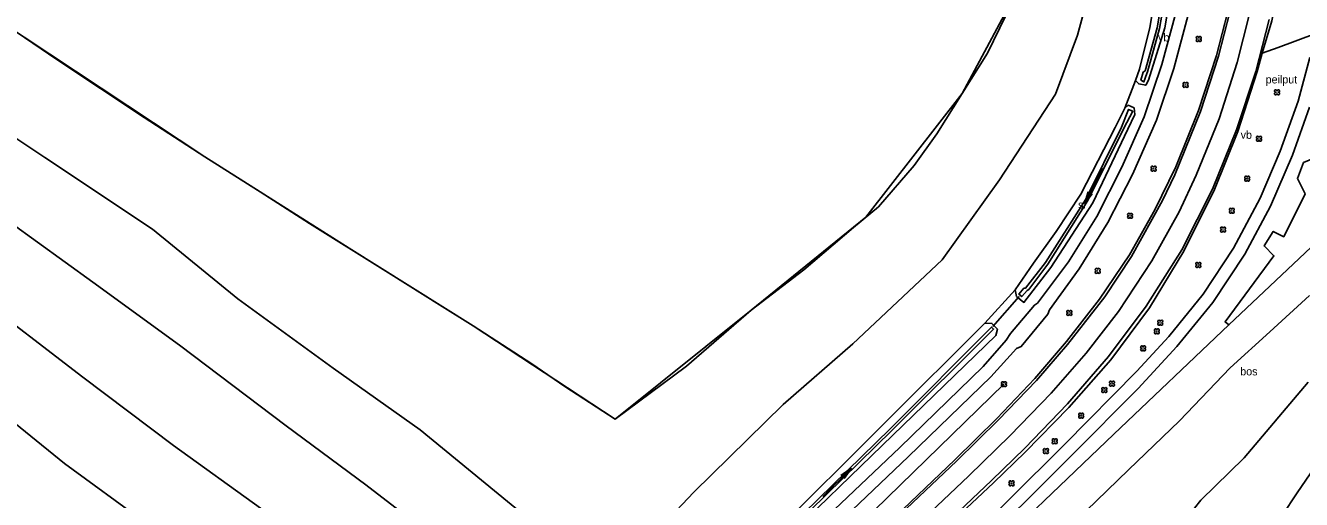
# Model space of a CAD drawing. Extents: x 154825 to 158680, y 370717 to 378075.
# Drawn here: x 157815 to 157974.4, y 372426.3 to 372485.5 of the extents above; entities that cross this region are included whole.
import ezdxf

# ---------------------------------------------------------------- set-up
doc = ezdxf.new("R2010")
doc.units = 0
for name, color, linetype in [('boom', 7, 'Continuous'), ('bos(vs)', 7, 'Continuous'), ('cultuurscheiding', 7, 'Continuous'), ('deelstreep(9-3)', 7, 'Continuous'), ('duiker lijn', 7, 'Continuous'), ('hoogteverschillijn', 7, 'Continuous'), ('insteek sloot', 7, 'Continuous'), ('kantstreep', 7, 'Continuous'), ('maaiveldlijn algemeen - gesloten verharding', 7, 'Continuous'), ('maaiveldlijn algemeen - open verharding', 7, 'Continuous'), ('peilput', 7, 'Continuous'), ('raster - hek', 7, 'Continuous'), ('Sloot bodem', 7, 'Continuous'), ('sloot(vs)', 7, 'Continuous'), ('stroomrichting  watergangen', 7, 'Continuous'), ('verkeersb_z kabel', 7, 'Continuous'), ('vlak_akkerland', 7, 'Continuous'), ('vlak_Bos', 7, 'Continuous'), ('vlak_Grazige_vegetatie', 7, 'Continuous')]:
    doc.layers.add(name, color=color, linetype=linetype)

msp = doc.modelspace()

# ---------------------------------------------------------------- linework, layer by layer
at = {"layer": 'boom'}
msp.add_lwpolyline([(157937.25, 372440.7), (157921.08, 372424.96), (157899.21, 372404.5)], dxfattribs=at)
for centre in [(157961.6, 372483.8), (157959.94, 372478.08), (157971.38, 372477.16), (157969.13, 372471.34), (157955.95, 372467.62), (157967.64, 372466.36), (157953.02, 372461.73), (157965.73, 372462.35), (157964.64, 372460.01), (157961.54, 372455.58), (157948.98, 372454.85), (157945.43, 372449.59), (157956.36, 372447.29), (157956.78, 372448.36), (157954.65, 372445.16), (157937.25, 372440.7), (157950.76, 372440.76), (157949.8, 372439.96), (157946.9, 372436.76), (157943.6, 372433.57), (157942.49, 372432.33), (157938.2, 372428.31)]:
    msp.add_circle(centre, 0.006, dxfattribs=at)
for centre, start, end in [((157961.44, 372483.96), 357.075, 272.925), ((157961.44, 372483.65), 87.075, 2.925), ((157961.75, 372483.96), 267.075, 182.925), ((157961.75, 372483.65), 177.075, 92.925), ((157959.78, 372478.24), 357.075, 272.925), ((157959.78, 372477.92), 87.075, 2.925), ((157960.1, 372478.24), 267.075, 182.925), ((157960.1, 372477.92), 177.075, 92.925), ((157971.22, 372477.31), 357.075, 272.925), ((157971.54, 372477.31), 267.075, 182.925), ((157971.22, 372477), 87.075, 2.925), ((157971.54, 372477), 177.075, 92.925), ((157968.97, 372471.5), 357.075, 272.925), ((157968.97, 372471.19), 87.075, 2.925), ((157969.29, 372471.5), 267.075, 182.925), ((157969.29, 372471.19), 177.075, 92.925), ((157955.79, 372467.77), 357.075, 272.925), ((157956.11, 372467.77), 267.075, 182.925), ((157955.79, 372467.46), 87.075, 2.925), ((157956.11, 372467.46), 177.075, 92.925), ((157967.49, 372466.52), 357.075, 272.925), ((157967.49, 372466.2), 87.075, 2.925), ((157967.8, 372466.52), 267.075, 182.925), ((157967.8, 372466.2), 177.075, 92.925), ((157952.86, 372461.88), 357.075, 272.925), ((157952.86, 372461.57), 87.075, 2.925), ((157953.17, 372461.88), 267.075, 182.925), ((157953.17, 372461.57), 177.075, 92.925), ((157965.57, 372462.51), 357.075, 272.925), ((157965.57, 372462.19), 87.075, 2.925), ((157965.88, 372462.51), 267.075, 182.925), ((157965.88, 372462.19), 177.075, 92.925), ((157964.48, 372460.17), 357.075, 272.925), ((157964.48, 372459.85), 87.075, 2.925), ((157964.8, 372460.17), 267.075, 182.925), ((157964.8, 372459.85), 177.075, 92.925), ((157948.82, 372455.01), 357.075, 272.925), ((157949.14, 372455.01), 267.075, 182.925), ((157961.38, 372455.74), 357.075, 272.925), ((157961.38, 372455.43), 87.075, 2.925), ((157961.7, 372455.74), 267.075, 182.925), ((157961.7, 372455.43), 177.075, 92.925), ((157948.82, 372454.69), 87.075, 2.925), ((157949.14, 372454.69), 177.075, 92.925), ((157945.27, 372449.75), 357.075, 272.925), ((157945.27, 372449.44), 87.075, 2.925), ((157945.59, 372449.75), 267.075, 182.925), ((157945.59, 372449.44), 177.075, 92.925), ((157956.62, 372448.52), 357.075, 272.925), ((157956.94, 372448.52), 267.075, 182.925), ((157956.2, 372447.45), 357.075, 272.925), ((157956.2, 372447.13), 87.075, 2.925), ((157956.51, 372447.45), 267.075, 182.925), ((157956.51, 372447.13), 177.075, 92.925), ((157956.62, 372448.2), 87.075, 2.925), ((157956.94, 372448.2), 177.075, 92.925), ((157954.49, 372445.32), 357.075, 272.925), ((157954.8, 372445.32), 267.075, 182.925), ((157954.49, 372445), 87.075, 2.925), ((157954.8, 372445), 177.075, 92.925), ((157937.09, 372440.85), 357.075, 272.925), ((157937.09, 372440.54), 87.075, 2.925), ((157937.41, 372440.85), 267.075, 182.925), ((157937.41, 372440.54), 177.075, 92.925), ((157950.6, 372440.91), 357.075, 272.925), ((157950.6, 372440.6), 87.075, 2.925), ((157950.92, 372440.91), 267.075, 182.925), ((157950.92, 372440.6), 177.075, 92.925), ((157949.64, 372440.11), 357.075, 272.925), ((157949.64, 372439.8), 87.075, 2.925), ((157949.96, 372440.11), 267.075, 182.925), ((157949.96, 372439.8), 177.075, 92.925), ((157946.75, 372436.92), 357.075, 272.925), ((157946.75, 372436.6), 87.075, 2.925), ((157947.06, 372436.92), 267.075, 182.925), ((157947.06, 372436.6), 177.075, 92.925), ((157943.45, 372433.72), 357.075, 272.925), ((157943.45, 372433.41), 87.075, 2.925), ((157943.76, 372433.72), 267.075, 182.925), ((157943.76, 372433.41), 177.075, 92.925), ((157942.33, 372432.49), 357.075, 272.925), ((157942.33, 372432.17), 87.075, 2.925), ((157942.65, 372432.49), 267.075, 182.925), ((157942.65, 372432.17), 177.075, 92.925), ((157938.04, 372428.47), 357.075, 272.925), ((157938.04, 372428.15), 87.075, 2.925), ((157938.36, 372428.47), 267.075, 182.925), ((157938.36, 372428.15), 177.075, 92.925)]:
    msp.add_arc(centre, 0.158, start, end, dxfattribs=at)
at = {"layer": 'bos(vs)'}
msp.add_lwpolyline([(157991.01, 372472.3), (157988.03, 372476.61), (157981.58, 372483.22), (157979.12, 372480.89), (157980.07, 372479.08), (157976.61, 372469.17), (157974.7, 372468.37), (157973.91, 372466.38), (157974.87, 372464.48), (157972.22, 372459.1), (157970.9, 372459.77), (157969.76, 372457.97), (157970.99, 372456.73), (157964.89, 372448.46), (157965.36, 372448.1)], dxfattribs=at)
at = {"layer": 'cultuurscheiding'}
for points in [[(157952.35, 372475.19), (157953.67, 372478.63)], [(157934.88, 372448.33), (157938.65, 372452.47)]]:
    msp.add_lwpolyline(points, dxfattribs=at)
at = {"layer": 'deelstreep(9-3)'}
msp.add_lwpolyline([(157967.9, 372486.8), (157966.4, 372480.87), (157964.14, 372473.83), (157961.28, 372466.81), (157959.13, 372462.23), (157955.73, 372456.1), (157951.58, 372449.77), (157947.51, 372444.57), (157943.17, 372439.56), (157938.03, 372434.28), (157932.88, 372429.26), (157917.8, 372414.96), (157900.57, 372398.73)], dxfattribs=at)
at = {"layer": 'duiker lijn'}
msp.add_lwpolyline([(157935.88, 372447.9), (157939.16, 372451.65)], dxfattribs=at)
at = {"layer": 'hoogteverschillijn'}
for points in [[(157949.06, 372493.97), (157946.43, 372484.27), (157943.68, 372476.9), (157936.71, 372466.22), (157929.52, 372456.21), (157918.38, 372445.73), (157909.69, 372438.14), (157898.49, 372427.19), (157888.26, 372416.39), (157876.85, 372424.72), (157864.32, 372434.98), (157853.47, 372442.68), (157841.56, 372451.35), (157830.89, 372460.06), (157817.44, 372469), (157806.91, 372476.01)], [(157810.8, 372486.76), (157818.91, 372481.27), (157829.84, 372473.99), (157837.4, 372469.1), (157844.34, 372464.74), (157850.48, 372460.77), (157860.38, 372454.6), (157867.08, 372450.39), (157870.96, 372447.97), (157878.26, 372443.24), (157882.38, 372440.39), (157888.67, 372436.33), (157897.61, 372442.95), (157905.68, 372449.95), (157912.26, 372454.96), (157918.46, 372460.25), (157921.59, 372462.85), (157926.05, 372468.02), (157928.88, 372471.98), (157935.2, 372482.04), (157939.78, 372491.5)], [(157881.47, 372407.9), (157872.69, 372415.27), (157866.4, 372421.3), (157857.53, 372428.1), (157847.58, 372435.5), (157834.25, 372445.57), (157823.42, 372453.44), (157813.05, 372460.94)], [(157808.27, 372452.22), (157822.19, 372441.57), (157833.49, 372433.04), (157844.36, 372425.2), (157854.75, 372417.01), (157862.66, 372410.39), (157874.45, 372400.64), (157866.59, 372392.5), (157855.13, 372401.58), (157847.65, 372408.81), (157837.38, 372416.14), (157829.91, 372423.46), (157819.89, 372430.77), (157810.1, 372438.7)], [(157975.42, 372451.75), (157970.46, 372447.24), (157965.5, 372442.73), (157959.18, 372436.11), (157952.82, 372429.98), (157944.87, 372422.31), (157934.73, 372412.55), (157929.45, 372407.46), (157937.32, 372400.74), (157942.35, 372406.7), (157949.83, 372413.18), (157956.32, 372419.2), (157961.87, 372426.2), (157967.28, 372431.48), (157975.28, 372440.95)], [(157983.15, 372370.82), (157972.8, 372377.86), (157967.18, 372381.36), (157958.84, 372386.99), (157945.2, 372395.77), (157958.44, 372407.85), (157965.25, 372414.93), (157970.16, 372421.45), (157973.9, 372427.12), (157978.77, 372434.26)]]:
    msp.add_lwpolyline(points, dxfattribs=at)
at = {"layer": 'insteek sloot'}
for points in [[(157954.19, 372539.22), (157953.23, 372540.06), (157952.94, 372539.09), (157953.29, 372537.7), (157955.47, 372527.74), (157956.42, 372522.74), (157957.47, 372512.36), (157957.5, 372502.78), (157956.95, 372493.75), (157955.48, 372485.23), (157954.2, 372480.04), (157953.67, 372478.63)], [(157953.67, 372478.63), (157954.1, 372478.2), (157954.97, 372478.04), (157955.3, 372478.66), (157957.37, 372485.22), (157958.74, 372493.47), (157959.47, 372502.93), (157959.54, 372512.25), (157958.49, 372522.7), (157957.48, 372527.63), (157955.84, 372533.76), (157954.62, 372537.88), (157954.19, 372539.22)], [(157938.65, 372452.47), (157938.83, 372451.66), (157939.75, 372450.9), (157943.12, 372455.26), (157948.34, 372463.35), (157952.74, 372472.54), (157953.6, 372474.39), (157953.51, 372475.2), (157952.78, 372475.53), (157952.35, 372475.19)], [(157952.35, 372475.19), (157951.17, 372472.75), (157946.88, 372464.44), (157943.76, 372459.76), (157940.93, 372455.81), (157938.65, 372452.47)], [(157893.76, 372408), (157893.83, 372407.41), (157894.35, 372406.92), (157894.88, 372407.08), (157908.69, 372420.09), (157923.39, 372434.34), (157936.24, 372446.79), (157936.43, 372447.55), (157935.76, 372448.29), (157934.88, 372448.33)], [(157893.76, 372408), (157908.11, 372421.68), (157922.48, 372435.99), (157934.88, 372448.33)]]:
    msp.add_lwpolyline(points, dxfattribs=at)
at = {"layer": 'kantstreep'}
for points in [[(157811.11, 372314.18), (157819.16, 372322.72), (157827.26, 372331.17), (157835.64, 372339.76), (157843.77, 372347.86), (157852.31, 372356.24), (157869.21, 372372.45), (157886.33, 372388.55), (157895.28, 372396.97), (157898.87, 372400.4), (157916.5, 372417.04), (157931.32, 372431.09), (157936.57, 372436.22), (157941.31, 372441.16), (157945.2, 372445.65), (157949.85, 372451.61), (157953.2, 372456.66), (157957.05, 372463.64), (157958.6, 372466.86), (157961.83, 372474.76), (157964.06, 372481.67), (157965.46, 372487.18)], [(157970.4, 372486.24), (157968.71, 372479.75), (157966.29, 372472.47), (157963.29, 372465.06), (157959.47, 372457.49), (157955.04, 372450.45), (157950.31, 372444.14), (157945.19, 372438.22), (157939.88, 372432.7), (157935.68, 372428.65), (157919.64, 372413.43), (157902.02, 372396.85), (157893.16, 372388.45), (157875.35, 372371.69), (157863.62, 372360.57), (157853.07, 372350.36), (157843.79, 372341.19), (157832.37, 372329.62), (157817.57, 372314.15), (157804.62, 372300.14)]]:
    msp.add_lwpolyline(points, dxfattribs=at)
at = {"layer": 'maaiveldlijn algemeen - gesloten verharding'}
for points in [[(157972.32, 372497.17), (157971.97, 372493.12), (157971.27, 372488.8), (157970.71, 372486.1), (157969.53, 372482.06)], [(157864.5, 372368.13), (157869.15, 372372.56), (157886.25, 372388.63), (157895.13, 372397.07), (157898.79, 372400.56), (157916.39, 372417.15), (157931.13, 372431.24), (157936.35, 372436.39), (157941.12, 372441.4), (157945.09, 372446.03), (157949.21, 372451.3), (157952.94, 372456.85), (157956.1, 372462.48), (157958.74, 372467.86), (157961.57, 372474.9), (157963.8, 372481.74), (157965.22, 372487.24), (157965.93, 372491.28), (157966.21, 372493.54), (157966.4, 372495.02)], [(157961.74, 372494.05), (157961.59, 372493.12), (157960.26, 372486.82), (157958.48, 372480.12), (157956.3, 372473.66), (157953.33, 372466.9), (157950.22, 372460.87), (157946.65, 372455.09), (157942.95, 372449.98), (157942.75, 372449.44), (157939.41, 372445.41), (157938.84, 372445.13), (157935.6, 372441.6), (157925.35, 372431.65), (157910.36, 372417.43), (157897.25, 372404.98), (157896.96, 372404.48), (157893.44, 372401.18), (157892.88, 372400.89), (157876.85, 372385.69), (157860.57, 372370.22), (157860.56, 372369.75)], [(157876.55, 372387.59), (157892.12, 372402.31), (157892.47, 372402.88), (157895.58, 372405.9), (157896.14, 372406.21), (157909.53, 372418.83), (157924.24, 372432.78), (157934.64, 372442.91), (157937.52, 372446.2), (157938.07, 372447.02), (157941.07, 372450.57), (157941.43, 372450.8), (157945.33, 372455.97), (157948.85, 372461.64), (157951.98, 372467.8), (157954.79, 372474.1), (157956.96, 372480.62), (157958.72, 372487.07)], [(157969.53, 372482.06), (157968.91, 372479.75), (157966.46, 372472.24), (157963.55, 372465), (157959.74, 372457.31), (157955.42, 372450.24), (157950.59, 372443.72), (157945.35, 372437.77), (157939.89, 372432.18), (157935.93, 372428.36), (157919.65, 372413.08), (157902.19, 372396.75), (157893.25, 372388.19), (157875.56, 372371.65), (157863.74, 372360.45), (157853.15, 372350.29), (157843.8, 372340.99), (157832.49, 372329.54), (157817.76, 372314.12), (157804.8, 372300.01), (157792.67, 372286.53), (157785.23, 372277.85), (157775.12, 372265.78), (157770.05, 372259.54)], [(157821.24, 372312.61), (157834, 372325.93), (157845.57, 372337.78), (157856.3, 372348.32), (157871.24, 372362.53), (157885.82, 372376.21), (157886.18, 372376.92), (157889.48, 372379.96), (157889.94, 372380.16), (157901.38, 372390.87), (157901.57, 372391.35), (157905.18, 372394.73), (157905.62, 372394.85), (157918.55, 372407.05), (157931.01, 372419.43), (157944.83, 372433.17), (157953.86, 372442.31), (157957.84, 372446.64), (157962.14, 372451.92), (157965.94, 372457.7), (157969.25, 372463.91), (157971.77, 372469.79), (157974.02, 372476.05), (157975.48, 372481.48)], [(157821.31, 372310.37), (157835.13, 372324.82), (157846.78, 372336.7), (157857.51, 372347.3), (157872.11, 372361.18), (157887.49, 372375.54), (157888.21, 372375.92), (157890.86, 372378.33), (157891.26, 372379.11), (157902.34, 372389.53), (157903.65, 372390.63), (157906.48, 372393.2), (157906.76, 372393.65), (157919.78, 372406.01), (157932.74, 372418.86), (157945.75, 372431.83), (157954.03, 372440.15), (157958.86, 372445.41), (157963.37, 372450.88), (157967.35, 372456.93), (157970.57, 372462.94), (157973.29, 372469.28), (157975.44, 372475.29)]]:
    msp.add_lwpolyline(points, dxfattribs=at)
at = {"layer": 'maaiveldlijn algemeen - open verharding'}
msp.add_lwpolyline([(157969.53, 372482.06), (157971.52, 372482.76), (157976.08, 372484.46)], dxfattribs=at)
at = {"layer": 'raster - hek'}
for points in [[(157991.01, 372472.3), (157965.36, 372448.1)], [(157965.36, 372448.1), (157951, 372434.44), (157932.61, 372416.87), (157926.64, 372411.07)]]:
    msp.add_lwpolyline(points, dxfattribs=at)
at = {"layer": 'Sloot bodem'}
for points in [[(157954.75, 372478.44), (157954.37, 372478.65), (157954.65, 372479.67), (157954.88, 372479.84), (157956.41, 372485.22), (157957.76, 372493.33), (157958.58, 372502.83), (157958.53, 372512.12), (157957.37, 372522.98), (157956.44, 372527.35), (157955.19, 372532.77), (157953.65, 372538.14), (157953.96, 372538.26), (157955.48, 372532.84), (157956.79, 372527.41), (157957.7, 372523.02), (157958.86, 372512.11), (157958.88, 372502.81), (157958.09, 372493.3), (157956.68, 372485.12), (157955.17, 372479.73), (157955.1, 372479.5), (157954.75, 372478.44)], [(157952.82, 372475.01), (157953.35, 372474.78), (157952.24, 372472.68), (157947.72, 372463.62), (157942.72, 372455.67), (157940.35, 372452.53), (157940.16, 372452.38), (157939.47, 372451.64), (157939.13, 372451.92), (157939.74, 372452.68), (157939.96, 372452.69), (157942.45, 372455.88), (157947.48, 372463.79), (157951.94, 372472.8), (157952.82, 372475.01)], [(157894.07, 372407.77), (157894.42, 372407.41), (157895.34, 372408.18), (157908.87, 372420.82), (157923.27, 372434.95), (157935.97, 372447.57), (157935.71, 372447.82), (157923.09, 372435.16), (157908.64, 372421.05), (157895.19, 372408.43), (157894.07, 372407.77)]]:
    msp.add_lwpolyline(points, dxfattribs=at)
at = {"layer": 'stroomrichting  watergangen'}
for p, q in [((157949.58, 372467.66), (157947.31, 372463.21)), ((157947.31, 372463.21), (157947.77, 372464.72)), ((157947.33, 372463.22), (157948.28, 372464.48)), ((157914.64, 372426.68), (157918.19, 372430.19)), ((157918.17, 372430.19), (157916.87, 372429.29)), ((157918.19, 372430.19), (157917.28, 372428.9))]:
    msp.add_line(p, q, dxfattribs=at)
at = {"layer": 'vlak_akkerland'}
for points in [[(157956.95, 372493.75), (157955.48, 372485.23), (157954.2, 372480.04), (157953.67, 372478.63), (157952.35, 372475.19), (157951.17, 372472.75), (157946.88, 372464.44), (157943.76, 372459.76), (157940.93, 372455.81), (157938.65, 372452.47), (157934.88, 372448.33), (157922.48, 372435.99), (157908.11, 372421.68)], [(157814.86, 372484.02), (157837.4, 372469.1), (157855.43, 372457.68), (157870.96, 372447.97), (157888.67, 372436.33), (157905.68, 372449.95), (157920.02, 372461.55), (157932.04, 372477.01), (157939.78, 372491.5)]]:
    msp.add_lwpolyline(points, dxfattribs=at)
at = {"layer": 'vlak_Bos'}
for points in [[(157980.08, 372320.43), (157974, 372324.62), (157970.2, 372327.32), (157984.17, 372346.6), (157927.5, 372410.28), (157926.64, 372411.07), (157932.61, 372416.87), (157951, 372434.44), (157965.36, 372448.1), (157964.89, 372448.46), (157970.99, 372456.73), (157969.76, 372457.97), (157970.9, 372459.77), (157972.22, 372459.1), (157974.87, 372464.48), (157973.91, 372466.38), (157974.7, 372468.37)], [(157978.77, 372434.26), (157973.9, 372427.12), (157970.16, 372421.45), (157965.25, 372414.93), (157958.44, 372407.85), (157958.84, 372386.99), (157967.18, 372381.36), (157972.8, 372377.86), (157983.15, 372370.82)]]:
    msp.add_lwpolyline(points, dxfattribs=at)
at = {"layer": 'vlak_Grazige_vegetatie'}
for points in [[(157954.19, 372539.22), (157954.62, 372537.88), (157955.84, 372533.76), (157957.48, 372527.63), (157958.49, 372522.7), (157959.54, 372512.25), (157959.47, 372502.93), (157958.74, 372493.47), (157957.37, 372485.22), (157955.3, 372478.66), (157954.97, 372478.04), (157954.1, 372478.2), (157953.67, 372478.63), (157954.2, 372480.04), (157955.48, 372485.23), (157956.95, 372493.75), (157957.5, 372502.78), (157957.47, 372512.36), (157956.42, 372522.74), (157955.47, 372527.74), (157953.29, 372537.7), (157952.94, 372539.09), (157953.23, 372540.06)], [(157954.37, 372478.65), (157954.75, 372478.44), (157955.1, 372479.5), (157955.17, 372479.73), (157956.68, 372485.12), (157958.09, 372493.3), (157958.88, 372502.81), (157958.86, 372512.11), (157957.7, 372523.02), (157956.79, 372527.41), (157955.48, 372532.84), (157953.96, 372538.26), (157953.65, 372538.14), (157955.19, 372532.77), (157956.44, 372527.35), (157957.37, 372522.98), (157958.53, 372512.12), (157958.58, 372502.83), (157957.76, 372493.33), (157956.41, 372485.22), (157954.88, 372479.84), (157954.65, 372479.67)], [(157953.51, 372475.2), (157953.6, 372474.39), (157952.74, 372472.54), (157948.34, 372463.35), (157943.12, 372455.26), (157939.75, 372450.9), (157938.83, 372451.66), (157938.65, 372452.47), (157940.93, 372455.81), (157943.76, 372459.76), (157946.88, 372464.44), (157951.17, 372472.75), (157952.35, 372475.19), (157952.78, 372475.53)], [(157939.13, 372451.92), (157939.47, 372451.64), (157940.16, 372452.38), (157940.35, 372452.53), (157942.72, 372455.67), (157947.72, 372463.62), (157952.24, 372472.68), (157953.35, 372474.78), (157952.82, 372475.01), (157951.94, 372472.8), (157947.48, 372463.79), (157942.45, 372455.88), (157939.96, 372452.69), (157939.74, 372452.68)], [(157935.76, 372448.29), (157936.43, 372447.55), (157936.24, 372446.79), (157923.39, 372434.34), (157908.69, 372420.09), (157894.88, 372407.08), (157894.35, 372406.92), (157893.83, 372407.41), (157893.76, 372408), (157908.11, 372421.68), (157922.48, 372435.99), (157934.88, 372448.33)], [(157894.07, 372407.77), (157894.42, 372407.41), (157895.34, 372408.18), (157908.87, 372420.82), (157923.27, 372434.95), (157935.97, 372447.57), (157935.71, 372447.82), (157923.09, 372435.16), (157908.64, 372421.05), (157895.19, 372408.43)]]:
    msp.add_lwpolyline(points, close=True, dxfattribs=at)
for points in [[(157908.69, 372420.09), (157923.39, 372434.34), (157936.24, 372446.79), (157936.43, 372447.55), (157935.76, 372448.29), (157934.88, 372448.33), (157938.65, 372452.47), (157938.83, 372451.66), (157939.75, 372450.9), (157943.12, 372455.26), (157948.34, 372463.35), (157952.74, 372472.54), (157953.6, 372474.39), (157953.51, 372475.2), (157952.78, 372475.53), (157952.35, 372475.19), (157953.67, 372478.63), (157954.1, 372478.2), (157954.97, 372478.04), (157955.3, 372478.66), (157957.37, 372485.22), (157958.74, 372493.47)], [(157958.72, 372487.07), (157956.96, 372480.62), (157954.79, 372474.1), (157951.98, 372467.8), (157948.85, 372461.64), (157945.33, 372455.97), (157941.43, 372450.8), (157941.07, 372450.57), (157938.07, 372447.02), (157937.52, 372446.2), (157934.64, 372442.91), (157924.24, 372432.78), (157909.53, 372418.83)], [(157965.22, 372487.24), (157963.8, 372481.74), (157961.57, 372474.9), (157958.74, 372467.86), (157956.1, 372462.48), (157952.94, 372456.85), (157949.21, 372451.3), (157945.09, 372446.03), (157941.12, 372441.4), (157936.35, 372436.39), (157931.13, 372431.24), (157916.39, 372417.15)], [(157910.36, 372417.43), (157925.35, 372431.65), (157935.6, 372441.6), (157938.84, 372445.13), (157939.41, 372445.41), (157942.75, 372449.44), (157942.95, 372449.98), (157946.65, 372455.09), (157950.22, 372460.87), (157953.33, 372466.9), (157956.3, 372473.66), (157958.48, 372480.12), (157960.26, 372486.82)], [(157804.8, 372300.01), (157817.76, 372314.12), (157832.49, 372329.54), (157843.8, 372340.99), (157853.15, 372350.29), (157863.74, 372360.45), (157875.56, 372371.65), (157893.25, 372388.19), (157902.19, 372396.75), (157919.65, 372413.08), (157935.93, 372428.36), (157939.89, 372432.18), (157945.35, 372437.77), (157950.59, 372443.72), (157955.42, 372450.24), (157959.74, 372457.31), (157963.55, 372465), (157966.46, 372472.24), (157968.91, 372479.75), (157969.53, 372482.06), (157971.52, 372482.76), (157976.08, 372484.46)], [(157975.48, 372481.48), (157974.02, 372476.05), (157971.77, 372469.79), (157969.25, 372463.91), (157965.94, 372457.7), (157962.14, 372451.92), (157957.84, 372446.64), (157953.86, 372442.31), (157944.83, 372433.17), (157931.01, 372419.43), (157918.55, 372407.05), (157905.62, 372394.85), (157905.18, 372394.73), (157901.57, 372391.35), (157901.38, 372390.87), (157889.94, 372380.16), (157889.48, 372379.96), (157886.18, 372376.92), (157885.82, 372376.21), (157871.24, 372362.53), (157856.3, 372348.32), (157845.57, 372337.78), (157834, 372325.93), (157821.24, 372312.61)], [(157821.31, 372310.37), (157835.13, 372324.82), (157846.78, 372336.7), (157857.51, 372347.3), (157872.11, 372361.18), (157887.49, 372375.54), (157888.21, 372375.92), (157890.86, 372378.33), (157891.26, 372379.11), (157902.34, 372389.53), (157903.65, 372390.63), (157906.48, 372393.2), (157906.76, 372393.65), (157919.78, 372406.01), (157932.74, 372418.86), (157945.75, 372431.83), (157954.03, 372440.15), (157958.86, 372445.41), (157963.37, 372450.88), (157967.35, 372456.93), (157970.57, 372462.94), (157973.29, 372469.28), (157975.44, 372475.29)], [(157974.7, 372468.37), (157973.91, 372466.38), (157974.87, 372464.48), (157972.22, 372459.1), (157970.9, 372459.77), (157969.76, 372457.97), (157970.99, 372456.73), (157964.89, 372448.46), (157965.36, 372448.1), (157951, 372434.44), (157932.61, 372416.87)]]:
    msp.add_lwpolyline(points, dxfattribs=at)

# ---------------------------------------------------------------- texts
at = {"layer": 'bos(vs)'}
msp.add_text('bos', height=1, dxfattribs=at).set_placement((157966.78, 372441.79))
at = {"layer": 'peilput'}
msp.add_text('peilput', height=1, dxfattribs=at).set_placement((157969.95, 372478.26))
at = {"layer": 'sloot(vs)'}
msp.add_text('sl', height=1, dxfattribs=at).set_placement((157946.52, 372462.61))
at = {"layer": 'verkeersb_z kabel'}
for p in [(157956.51, 372483.51), (157966.83, 372471.34)]:
    msp.add_text('vb', height=1, dxfattribs=at).set_placement(p)

doc.saveas('drawing.dxf')
